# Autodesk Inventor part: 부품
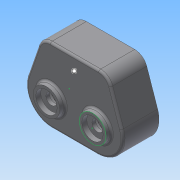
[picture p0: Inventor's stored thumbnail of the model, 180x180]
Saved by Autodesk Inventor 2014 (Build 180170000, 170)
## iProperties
Created: 2014-12
Part Number: 부품
Material: 일반
Document SubType Name: Modeling
Designer: net
Density: 1 g/cm^3
Appearance: 기본값
Author: net
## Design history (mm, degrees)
sketch "스케치1"
  geometry: L1 (-47, 36)-(47, 36); L2 (47, 36)-(66.565, -20.803); L3 (-47, 36)-(-66.565, -20.803); L4 (-32.527, -68.527)-(32.527, -68.527); L5 (0, 0)-(-32.527, -32.527); L6 (0, 0)-(0, -68.527); A1 r 36 centre (-32.527, -32.527) between (-66.565, -20.803) and (-32.527, -68.527); A2 r 36 centre (32.527, -32.527) between (32.527, -68.527) and (66.565, -20.803); A3 r 46 centre (0, 0) between (-32.527, -32.527) and (32.527, -32.527); 2 further points
  constraints: 12 end point, 6 point on circle, 3 centre point, 3 tangent, 2 midpoint, 1 coincident, 1 equal radius, 1 horizontal, 1 horizontal alignment, 1 parallel, 1 perpendicular, 1 vertical alignment
  dimensions: "d16" = 46 radius of A3; "d17" = 45 deg angle of L6 L5; "d18" = 36 radius of A1; "d19" = 94 distance of L1.start L1.end; "d20" = 36 distance from line of point (0, 0) L1
extrude "돌출1" new body sketch "스케치1" distance "d21" = 51; taper "d22" = 0 deg
fillet "모깎기1" dims "d23" = 18
fillet "모깎기2" dims "d24" = 3
sketch "스케치2"
  geometry: C1 r 20 at (-32.527, -32.527); C2 r 20 at (32.527, -32.527); A1 r 33 centre (-32.527, -32.527) between (-63.728, -21.78) and (-32.527, -65.527) reference; A2 r 33 centre (32.527, -32.527) between (32.527, -65.527) and (63.728, -21.78) reference; 1 further point
  constraints: 2 centre point, 2 coincident, 1 equal radius
  dimensions: "d25" = 40 diameter of C1
extrude "돌출2" join sketch "스케치2" distance "d26" = 7; taper "d27" = -10 deg
feature "쉘1" dims "d40" = 5
sketch "스케치5"
  geometry: C1 r 15.805 at (66.689, -63.527) reference; C2 r 15.805 at (1.635, -63.527) reference; C3 r 24 at (1.635, -63.527); C4 r 24 at (66.689, -63.527); 1 further point
  constraints: 2 centre point, 2 coincident, 1 equal radius
  dimensions: "d61" = 48 diameter of C3
extrude "돌출3" join sketch "스케치5" distance "d62" = 11; taper "d63" = 0 deg
node "작업 평면1"
sketch "스케치6"
  geometry: C1 r 18.766 at (0, 0) reference; 1 further point
sketch "스케치7"
  geometry: C1 r 15.805 at (0, 0) reference; C2 r 24 at (0, 0) reference; C3 r 15.805 at (0, 0); 1 further point
  constraints: 1 centre point, 1 coincident, 1 concentric
extrude "돌출4" join sketch "스케치7" stored distance "d65" = 10; taper "d66" = 0 deg
hole "구멍4" diameter "d69" = 15.5; stored, may be unused: countersink angle "d73" = 90 deg, drill point angle "d75" = 118 deg; dims "d67" = 10, "d68" = 10, "d70" = 6, "d71" = 30, "d72" = 7, "d74" = 21
sketch "스케치8"
  geometry: 1 further point
sketch "스케치9"
  geometry: 1 further point
fillet "모깎기3" dims "d76" = 3
hole "구멍5" diameter "d79" = 35; stored, may be unused: countersink angle "d83" = 90 deg, drill point angle "d85" = 0 deg; dims "d77" = 10, "d78" = 10, "d80" = 6, "d81" = 4, "d82" = 2, "d84" = 11
fillet "모깎기4" dims "d86" = 3
sketch "스케치10"
  geometry: C1 r 15.805 at (0, 0) reference; C2 r 24 at (0, 0) reference; C3 r 15.805 at (0, 0); 1 further point
  constraints: 1 centre point, 1 coincident, 1 concentric
extrude "돌출5" join sketch "스케치10" stored distance "d87" = 10; taper "d88" = 0 deg
fillet "모깎기5" dims "d89" = 3
sketch "스케치11"
  geometry: C1 r 24 at (34.162, -31); C2 r 24 at (66.689, -63.527) reference; 1 further point
  constraints: 1 centre point, 1 coincident, 1 equal radius
chamfer "모따기1" distance "d90" = 1; stored, may be unused: second distance "d91" = 2, angle "d92" = 45 deg
chamfer "모따기2" distance "d93" = 1; stored, may be unused: second distance "d94" = 2, angle "d95" = 45 deg
extrude "돌출6" join sketch "스케치11" distance "d96" = 11; taper "d97" = 0 deg
hole "구멍6" diameter "d100" = 35; stored, may be unused: countersink angle "d104" = 90 deg, drill point angle "d106" = 0 deg; dims "d98" = 10, "d99" = 10, "d101" = 6, "d102" = 30, "d103" = 1, "d105" = 11
sketch "스케치12"
  geometry: L1 (66.689, -94.527)-(1.635, -94.527) reference; L2 (80.615, -8.767)-(95.999, -53.432) reference; L3 (0, 0)-(68.324, 0) reference; L4 (-27.675, -53.432)-(-12.291, -8.767) reference; C1 r 24 at (66.689, -63.527) reference; C2 r 27 at (1.635, -63.527) reference; A1 r 31 centre (1.635, -63.527) between (-27.675, -53.432) and (1.635, -94.527) reference; A2 r 31 centre (66.689, -63.527) between (66.689, -94.527) and (95.999, -53.432) reference; A3 r 13 centre (68.324, -13) between (80.615, -8.767) and (68.324, 0) reference; A4 r 13 centre (0, -13) between (0, 0) and (-12.291, -8.767) reference; 1 further point
hole "구멍3" diameter "d54" = 30; stored, may be unused: countersink angle "d58" = 90 deg, drill point angle "d60" = 118 deg; dims "d50" = 10, "d51" = 10, "d55" = 6, "d56" = 30, "d57" = 7, "d59" = 7
hole "구멍2" diameter "d43" = 15.5; stored, may be unused: countersink angle "d47" = 90 deg, drill point angle "d49" = 118 deg; dims "d44" = 6, "d45" = 30, "d46" = 7, "d48" = 10, "d52" = 10, "d53" = 10
sketch "스케치4"
  geometry: L1 (34.162, 36)-(-34.162, 36) reference; L2 (-51.181, 23.862)-(-66.565, -20.803) reference; L3 (-32.527, -68.527)-(32.527, -68.527) reference; L4 (66.565, -20.803)-(51.181, 23.862) reference; L5 (-34.162, 30)-(34.162, 30); L6 (45.508, 21.908)-(60.892, -22.757); L7 (32.527, -62.527)-(-32.527, -62.527); L8 (-60.892, -22.757)-(-45.508, 21.908); A1 r 18 centre (34.162, 18) between (51.181, 23.862) and (34.162, 36) reference; A2 r 18 centre (-34.162, 18) between (-34.162, 36) and (-51.181, 23.862) reference; A3 r 36 centre (-32.527, -32.527) between (-66.565, -20.803) and (-32.527, -68.527) reference; A4 r 36 centre (32.527, -32.527) between (32.527, -68.527) and (66.565, -20.803) reference; A5 r 12 centre (34.162, 18) between (45.508, 21.908) and (34.162, 30); A6 r 30 centre (32.527, -32.527) between (32.527, -62.527) and (60.892, -22.757); A7 r 30 centre (-32.527, -32.527) between (-60.892, -22.757) and (-32.527, -62.527); A8 r 12 centre (-34.162, 18) between (-34.162, 30) and (-45.508, 21.908); 1 further point
  constraints: 8 end point, 8 point on circle, 4 centre point, 7 other
  dimensions: "d39" = 6 distance between parallel lines of L1 L5
sketch "스케치3"
  geometry: 1 further point
node "솔리드1"
mirror "대칭2"
mirror "대칭3"
mirror "대칭4"
other parameters: "d107" = 0
